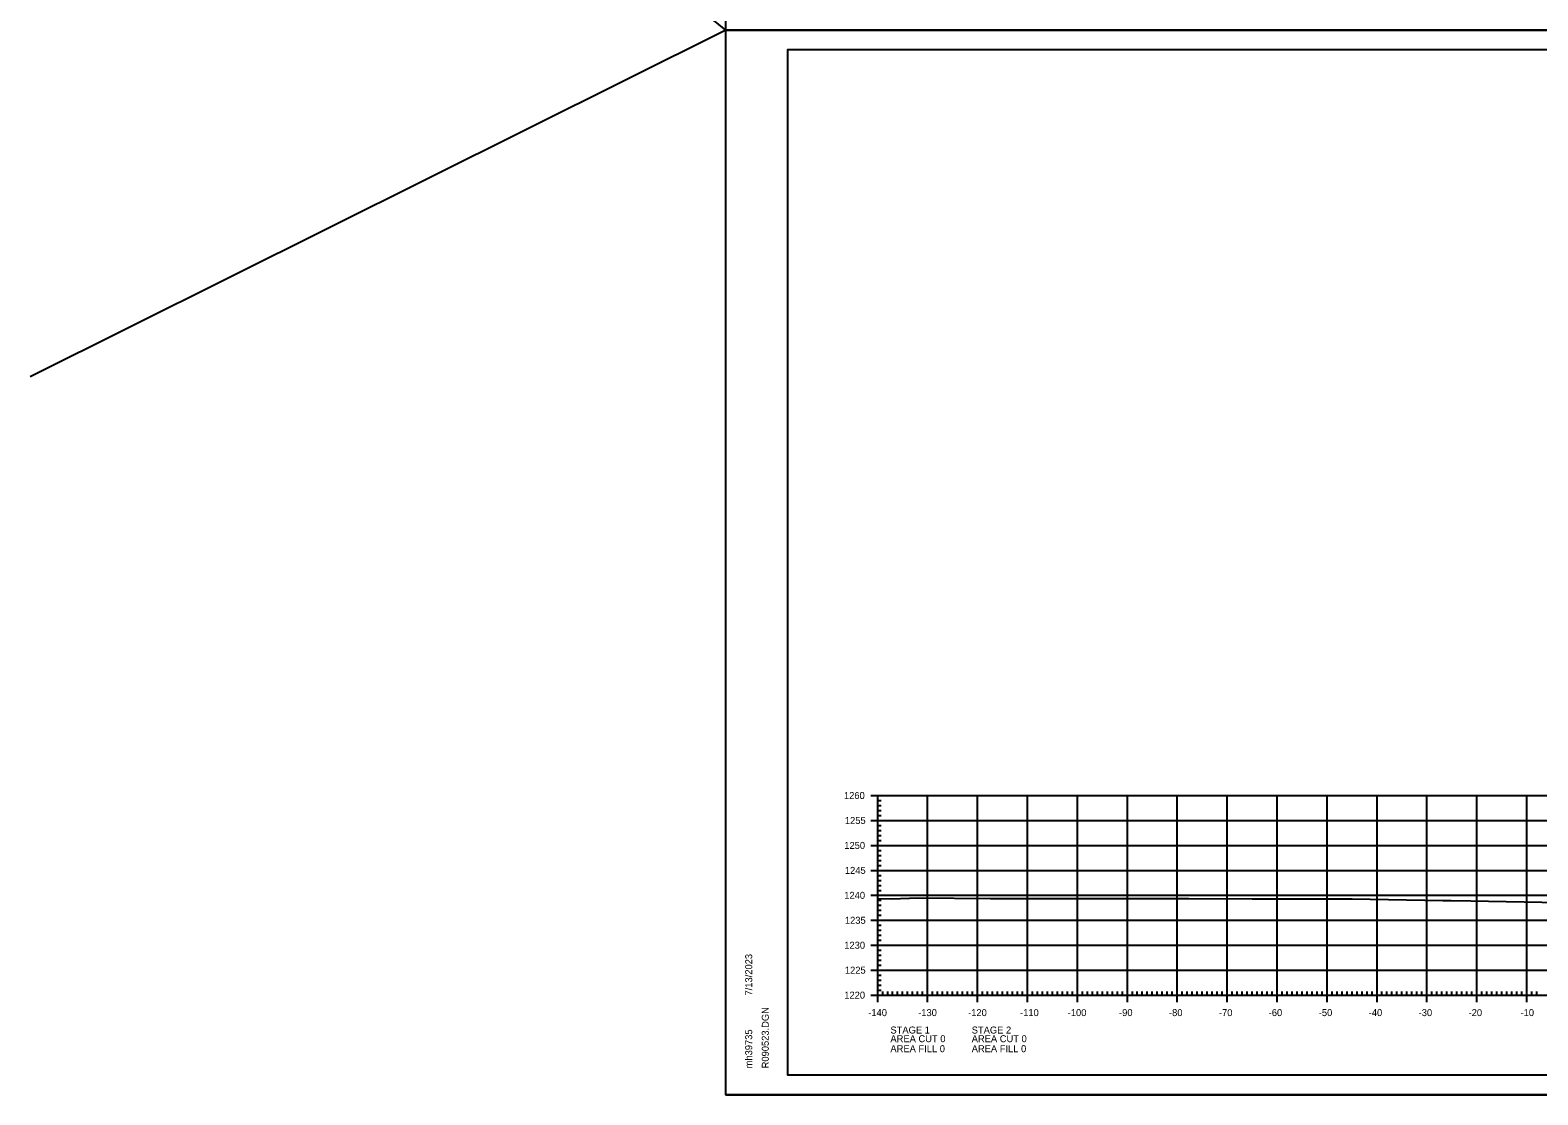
# Model space of a CAD drawing. Extents: x 1406028 to 1412453, y 321733 to 325986.
# Drawn here: x 1406280.1 to 1406582.1, y 322786 to 322999.4 of the extents above; entities that cross this region are included whole.
import ezdxf

# ---------------------------------------------------------------- set-up
doc = ezdxf.new("R2010")
doc.units = 0
for name, color, linetype in [('R_Axis', 7, 'Continuous'), ('R_Axis Annot', 7, 'Continuous'), ('R_Border', 7, 'Continuous'), ('R_Exist Surface', 7, 'Continuous'), ('R_Grid', 7, 'Continuous'), ('R_No Plot', 7, 'Continuous'), ('R_Water', 7, 'Continuous')]:
    doc.layers.add(name, color=color, linetype=linetype)

msp = doc.modelspace()

# ---------------------------------------------------------------- linework, layer by layer
at = {"layer": 'R_Axis'}
for p, q in [((1406448.48, 322846), (1406451.28, 322846)), ((1406449.88, 322806), (1406449.88, 322846)), ((1406449.88, 322845), (1406450.58, 322845)), ((1406449.88, 322844), (1406450.58, 322844)), ((1406449.88, 322843), (1406450.58, 322843)), ((1406448.48, 322841), (1406451.28, 322841)), ((1406449.88, 322842), (1406450.58, 322842)), ((1406449.88, 322840), (1406450.58, 322840)), ((1406449.88, 322839), (1406450.58, 322839)), ((1406449.88, 322838), (1406450.58, 322838)), ((1406449.88, 322837), (1406450.58, 322837)), ((1406448.48, 322836), (1406451.28, 322836)), ((1406449.88, 322835), (1406450.58, 322835)), ((1406449.88, 322834), (1406450.58, 322834)), ((1406448.48, 322831), (1406451.28, 322831)), ((1406449.88, 322833), (1406450.58, 322833)), ((1406449.88, 322832), (1406450.58, 322832)), ((1406449.88, 322830), (1406450.58, 322830)), ((1406449.88, 322829), (1406450.58, 322829)), ((1406449.88, 322828), (1406450.58, 322828)), ((1406448.48, 322826), (1406451.28, 322826)), ((1406449.88, 322827), (1406450.58, 322827)), ((1406449.88, 322825), (1406450.58, 322825)), ((1406449.88, 322824), (1406450.58, 322824)), ((1406449.88, 322823), (1406450.58, 322823)), ((1406449.88, 322822), (1406450.58, 322822)), ((1406448.48, 322821), (1406451.28, 322821)), ((1406449.88, 322820), (1406450.58, 322820)), ((1406449.88, 322819), (1406450.58, 322819)), ((1406448.48, 322816), (1406451.28, 322816)), ((1406449.88, 322818), (1406450.58, 322818)), ((1406449.88, 322817), (1406450.58, 322817)), ((1406449.88, 322815), (1406450.58, 322815)), ((1406449.88, 322814), (1406450.58, 322814)), ((1406449.88, 322813), (1406450.58, 322813)), ((1406448.48, 322811), (1406451.28, 322811)), ((1406449.88, 322812), (1406450.58, 322812)), ((1406449.88, 322810), (1406450.58, 322810)), ((1406449.88, 322809), (1406450.58, 322809)), ((1406449.88, 322808), (1406450.58, 322808)), ((1406449.88, 322804.6), (1406449.88, 322807.4)), ((1406449.88, 322807), (1406450.58, 322807)), ((1406450.88, 322806), (1406450.88, 322806.7)), ((1406451.88, 322806), (1406451.88, 322806.7)), ((1406452.88, 322806), (1406452.88, 322806.7)), ((1406453.88, 322806), (1406453.88, 322806.7)), ((1406454.88, 322806), (1406454.88, 322806.7)), ((1406455.88, 322806), (1406455.88, 322806.7)), ((1406456.88, 322806), (1406456.88, 322806.7)), ((1406457.88, 322806), (1406457.88, 322806.7)), ((1406458.88, 322806), (1406458.88, 322806.7)), ((1406459.88, 322804.6), (1406459.88, 322807.4)), ((1406460.88, 322806), (1406460.88, 322806.7)), ((1406461.88, 322806), (1406461.88, 322806.7)), ((1406462.88, 322806), (1406462.88, 322806.7)), ((1406463.88, 322806), (1406463.88, 322806.7)), ((1406464.88, 322806), (1406464.88, 322806.7)), ((1406465.88, 322806), (1406465.88, 322806.7)), ((1406466.88, 322806), (1406466.88, 322806.7)), ((1406467.88, 322806), (1406467.88, 322806.7)), ((1406468.88, 322806), (1406468.88, 322806.7)), ((1406469.88, 322804.6), (1406469.88, 322807.4)), ((1406470.88, 322806), (1406470.88, 322806.7)), ((1406471.88, 322806), (1406471.88, 322806.7)), ((1406472.88, 322806), (1406472.88, 322806.7)), ((1406473.88, 322806), (1406473.88, 322806.7)), ((1406474.88, 322806), (1406474.88, 322806.7)), ((1406475.88, 322806), (1406475.88, 322806.7)), ((1406476.88, 322806), (1406476.88, 322806.7)), ((1406477.88, 322806), (1406477.88, 322806.7)), ((1406478.88, 322806), (1406478.88, 322806.7)), ((1406479.88, 322804.6), (1406479.88, 322807.4)), ((1406480.88, 322806), (1406480.88, 322806.7)), ((1406481.88, 322806), (1406481.88, 322806.7)), ((1406482.88, 322806), (1406482.88, 322806.7)), ((1406483.88, 322806), (1406483.88, 322806.7)), ((1406484.88, 322806), (1406484.88, 322806.7)), ((1406485.88, 322806), (1406485.88, 322806.7)), ((1406486.88, 322806), (1406486.88, 322806.7)), ((1406487.88, 322806), (1406487.88, 322806.7)), ((1406488.88, 322806), (1406488.88, 322806.7)), ((1406489.88, 322804.6), (1406489.88, 322807.4)), ((1406490.88, 322806), (1406490.88, 322806.7)), ((1406491.88, 322806), (1406491.88, 322806.7)), ((1406492.88, 322806), (1406492.88, 322806.7)), ((1406493.88, 322806), (1406493.88, 322806.7)), ((1406494.88, 322806), (1406494.88, 322806.7)), ((1406495.88, 322806), (1406495.88, 322806.7)), ((1406496.88, 322806), (1406496.88, 322806.7)), ((1406497.88, 322806), (1406497.88, 322806.7)), ((1406498.88, 322806), (1406498.88, 322806.7)), ((1406499.88, 322804.6), (1406499.88, 322807.4)), ((1406500.88, 322806), (1406500.88, 322806.7)), ((1406501.88, 322806), (1406501.88, 322806.7)), ((1406502.88, 322806), (1406502.88, 322806.7)), ((1406503.88, 322806), (1406503.88, 322806.7)), ((1406504.88, 322806), (1406504.88, 322806.7)), ((1406505.88, 322806), (1406505.88, 322806.7)), ((1406506.88, 322806), (1406506.88, 322806.7)), ((1406507.88, 322806), (1406507.88, 322806.7)), ((1406508.88, 322806), (1406508.88, 322806.7)), ((1406509.88, 322804.6), (1406509.88, 322807.4)), ((1406510.88, 322806), (1406510.88, 322806.7)), ((1406511.88, 322806), (1406511.88, 322806.7)), ((1406512.88, 322806), (1406512.88, 322806.7)), ((1406513.88, 322806), (1406513.88, 322806.7)), ((1406514.88, 322806), (1406514.88, 322806.7)), ((1406515.88, 322806), (1406515.88, 322806.7)), ((1406516.88, 322806), (1406516.88, 322806.7)), ((1406517.88, 322806), (1406517.88, 322806.7)), ((1406518.88, 322806), (1406518.88, 322806.7)), ((1406519.88, 322804.6), (1406519.88, 322807.4)), ((1406520.88, 322806), (1406520.88, 322806.7)), ((1406521.88, 322806), (1406521.88, 322806.7)), ((1406522.88, 322806), (1406522.88, 322806.7)), ((1406523.88, 322806), (1406523.88, 322806.7)), ((1406524.88, 322806), (1406524.88, 322806.7)), ((1406525.88, 322806), (1406525.88, 322806.7)), ((1406526.88, 322806), (1406526.88, 322806.7)), ((1406527.88, 322806), (1406527.88, 322806.7)), ((1406528.88, 322806), (1406528.88, 322806.7)), ((1406529.88, 322804.6), (1406529.88, 322807.4)), ((1406530.88, 322806), (1406530.88, 322806.7)), ((1406531.88, 322806), (1406531.88, 322806.7)), ((1406532.88, 322806), (1406532.88, 322806.7)), ((1406533.88, 322806), (1406533.88, 322806.7)), ((1406534.88, 322806), (1406534.88, 322806.7)), ((1406535.88, 322806), (1406535.88, 322806.7)), ((1406536.88, 322806), (1406536.88, 322806.7)), ((1406537.88, 322806), (1406537.88, 322806.7)), ((1406538.88, 322806), (1406538.88, 322806.7)), ((1406539.88, 322804.6), (1406539.88, 322807.4)), ((1406540.88, 322806), (1406540.88, 322806.7)), ((1406541.88, 322806), (1406541.88, 322806.7)), ((1406542.88, 322806), (1406542.88, 322806.7)), ((1406543.88, 322806), (1406543.88, 322806.7)), ((1406544.88, 322806), (1406544.88, 322806.7)), ((1406545.88, 322806), (1406545.88, 322806.7)), ((1406546.88, 322806), (1406546.88, 322806.7)), ((1406547.88, 322806), (1406547.88, 322806.7)), ((1406548.88, 322806), (1406548.88, 322806.7)), ((1406549.88, 322804.6), (1406549.88, 322807.4)), ((1406550.88, 322806), (1406550.88, 322806.7)), ((1406551.88, 322806), (1406551.88, 322806.7)), ((1406552.88, 322806), (1406552.88, 322806.7)), ((1406553.88, 322806), (1406553.88, 322806.7)), ((1406554.88, 322806), (1406554.88, 322806.7)), ((1406555.88, 322806), (1406555.88, 322806.7)), ((1406556.88, 322806), (1406556.88, 322806.7)), ((1406557.88, 322806), (1406557.88, 322806.7)), ((1406558.88, 322806), (1406558.88, 322806.7)), ((1406559.88, 322804.6), (1406559.88, 322807.4)), ((1406560.88, 322806), (1406560.88, 322806.7)), ((1406561.88, 322806), (1406561.88, 322806.7)), ((1406562.88, 322806), (1406562.88, 322806.7)), ((1406563.88, 322806), (1406563.88, 322806.7)), ((1406564.88, 322806), (1406564.88, 322806.7)), ((1406565.88, 322806), (1406565.88, 322806.7)), ((1406566.88, 322806), (1406566.88, 322806.7)), ((1406567.88, 322806), (1406567.88, 322806.7)), ((1406568.88, 322806), (1406568.88, 322806.7)), ((1406569.88, 322804.6), (1406569.88, 322807.4)), ((1406570.88, 322806), (1406570.88, 322806.7)), ((1406571.88, 322806), (1406571.88, 322806.7)), ((1406572.88, 322806), (1406572.88, 322806.7)), ((1406573.88, 322806), (1406573.88, 322806.7)), ((1406574.88, 322806), (1406574.88, 322806.7)), ((1406575.88, 322806), (1406575.88, 322806.7)), ((1406576.88, 322806), (1406576.88, 322806.7)), ((1406577.88, 322806), (1406577.88, 322806.7)), ((1406578.88, 322806), (1406578.88, 322806.7)), ((1406579.88, 322804.6), (1406579.88, 322807.4)), ((1406580.88, 322806), (1406580.88, 322806.7)), ((1406581.88, 322806), (1406581.88, 322806.7)), ((1406448.48, 322806), (1406451.28, 322806)), ((1406449.88, 322806), (1406729.88, 322806))]:
    msp.add_line(p, q, dxfattribs=at)
at = {"layer": 'R_Border'}
for p, q in [((1406431.88, 322995.46), (1406748.06, 322995.46)), ((1406431.88, 322790), (1406431.88, 322995.46)), ((1406431.88, 322790), (1406431.88, 322790)), ((1406748.06, 322790), (1406431.88, 322790))]:
    msp.add_line(p, q, dxfattribs=at)
at = {"layer": 'R_Exist Surface'}
msp.add_lwpolyline([(1406449.88, 322825.38), (1406452.7, 322825.28), (1406458.01, 322825.51), (1406472.46, 322825.38), (1406478.33, 322825.39), (1406489.83, 322825.36), (1406495.24, 322825.36), (1406507.3, 322825.34), (1406512.17, 322825.34), (1406524.9, 322825.31), (1406529.13, 322825.31), (1406542.66, 322825.27), (1406544.9, 322825.3), (1406563.06, 322824.95), (1406564.71, 322824.95), (1406568.7, 322824.91), (1406586.42, 322824.55)], dxfattribs=at)
at = {"layer": 'R_Grid'}
for p, q in [((1406449.88, 322846), (1406729.88, 322846)), ((1406449.88, 322806), (1406449.88, 322846)), ((1406459.88, 322806), (1406459.88, 322846)), ((1406469.88, 322806), (1406469.88, 322846)), ((1406479.88, 322806), (1406479.88, 322846)), ((1406489.88, 322806), (1406489.88, 322846)), ((1406499.88, 322806), (1406499.88, 322846)), ((1406509.88, 322806), (1406509.88, 322846)), ((1406519.88, 322806), (1406519.88, 322846)), ((1406529.88, 322806), (1406529.88, 322846)), ((1406539.88, 322806), (1406539.88, 322846)), ((1406549.88, 322806), (1406549.88, 322846)), ((1406559.88, 322806), (1406559.88, 322846)), ((1406569.88, 322806), (1406569.88, 322846)), ((1406579.88, 322806), (1406579.88, 322846)), ((1406449.88, 322841), (1406729.88, 322841)), ((1406449.88, 322836), (1406729.88, 322836)), ((1406449.88, 322831), (1406729.88, 322831)), ((1406449.88, 322826), (1406729.88, 322826)), ((1406449.88, 322821), (1406729.88, 322821)), ((1406449.88, 322816), (1406729.88, 322816)), ((1406449.88, 322811), (1406729.88, 322811)), ((1406449.88, 322806), (1406729.88, 322806))]:
    msp.add_line(p, q, dxfattribs=at)
at = {"layer": 'R_No Plot'}
for p, q in [((1406419.48, 322999.36), (1406752.82, 322999.36)), ((1406419.48, 322786.02), (1406752.82, 322786.02))]:
    msp.add_line(p, q, dxfattribs=at)
for points in [[(1406419.48, 323212.7), (1406752.82, 323212.7), (1406752.82, 322999.36), (1406419.48, 322999.36)], [(1406419.48, 322999.36), (1406752.82, 322999.36), (1406752.82, 322786.02), (1406419.48, 322786.02)], [(1406665.8, 322995.46), (1406685.42, 322995.46), (1406685.42, 322985.58), (1406701.54, 322985.58), (1406724.73, 322985.58), (1406724.73, 322961.25), (1406748.06, 322961.25), (1406748.06, 322790), (1406431.88, 322790), (1406431.88, 322995.46)]]:
    msp.add_lwpolyline(points, close=True, dxfattribs=at)
at = {"layer": 'R_Water'}
for q in [(1406288.14, 323105.96), (1406280.14, 322929.92)]:
    msp.add_line((1406419.48, 322999.36), q, dxfattribs=at)

# ---------------------------------------------------------------- texts
at = {"layer": 'R_Axis Annot'}
for s, p in [('1260', (1406443.13, 322845.3)), ('1255', (1406443.31, 322840.3)), ('1250', (1406443.19, 322835.3)), ('1245', (1406443.31, 322830.3)), ('1240', (1406443.19, 322825.3)), ('1235', (1406443.31, 322820.3)), ('1230', (1406443.19, 322815.3)), ('1225', (1406443.31, 322810.3)), ('1220', (1406443.19, 322805.3)), ('-140', (1406447.99, 322801.8)), ('-130', (1406457.99, 322801.8)), ('-120', (1406467.99, 322801.8)), ('-110', (1406478.39, 322801.8)), ('-100', (1406487.94, 322801.8)), ('-90', (1406498.22, 322801.8)), ('-80', (1406508.22, 322801.8)), ('-70', (1406518.22, 322801.8)), ('-60', (1406528.19, 322801.8)), ('-50', (1406538.22, 322801.8)), ('-40', (1406548.22, 322801.8)), ('-30', (1406558.22, 322801.8)), ('-20', (1406568.22, 322801.8)), ('-10', (1406578.62, 322801.8)), ('AREA CUT 0', (1406452.43, 322796.57)), ('STAGE 1', (1406452.43, 322798.31)), ('AREA CUT 0', (1406468.71, 322796.57)), ('STAGE 2', (1406468.71, 322798.31)), ('AREA FILL 0', (1406452.43, 322794.57)), ('AREA FILL 0', (1406468.71, 322794.57))]:
    msp.add_text(s, height=1.4, dxfattribs=at).set_placement(p)
at = {"layer": 'R_Border'}
for s, p in [('7/13/2023', (1406424.75, 322805.93)), ('R090523.DGN', (1406428.07, 322791.33)), ('mh39735', (1406424.75, 322791.33))]:
    msp.add_text(s, height=1.4, rotation=90, dxfattribs=at).set_placement(p)
at = {"layer": 'R_No Plot'}
msp.add_text('+', height=0.1, dxfattribs=at).set_placement((1406457.97, 322825.46))

doc.saveas('drawing.dxf')
